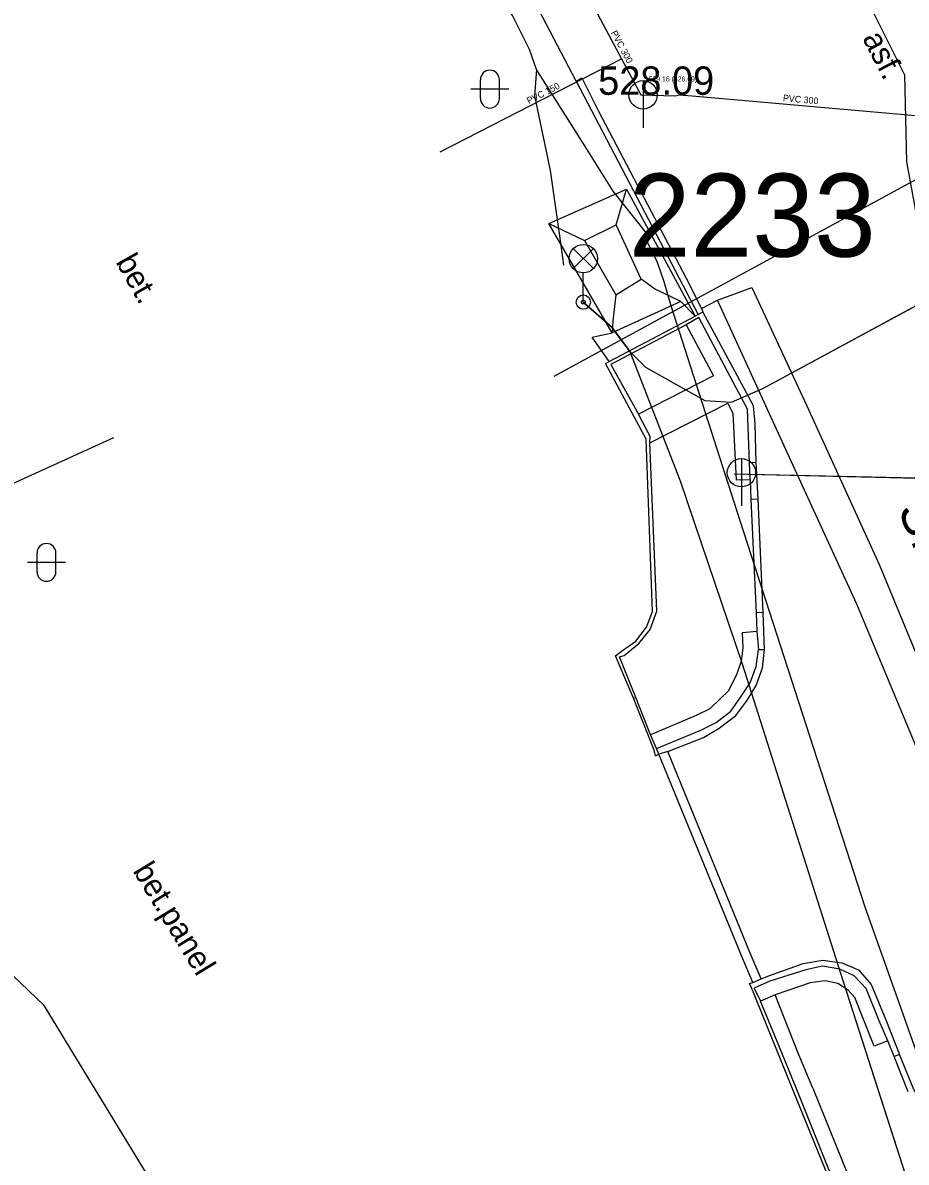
# Model space of a CAD drawing. Extents: x -669393 to -668650, y -1126925 to -1126294.
# Drawn here: x -669014.21 to -668990.85, y -1126829.82 to -1126799.71 of the extents above; entities that cross this region are included whole.
import ezdxf

# ---------------------------------------------------------------- set-up
doc = ezdxf.new("R2010")
doc.units = 0
for name, color, linetype in [('G_Bod_tecka', 7, 'Continuous'), ('G_Bod_vyska', 7, 'Continuous'), ('G_Cesty_Schody', 7, 'Continuous'), ('G_Objekty_technicke', 7, 'Continuous'), ('G_Plochy_zpevnene', 7, 'Continuous'), ('G_Popisy_Nazvy', 7, 'Continuous'), ('G_Popisy_povrchu', 7, 'Continuous'), ('G_Site-kanalizace', 7, 'Continuous'), ('G_Site-vodovod', 7, 'Continuous'), ('G_Z_ELsilove_podz_kotovane', 7, 'Continuous'), ('G_Z_KANAL_podz_kotovane', 7, 'Continuous'), ('G_Z_KANAL_podz_priblizne', 7, 'Continuous'), ('G_Z_PLYNY_podz_geodeticky', 7, 'Continuous'), ('G_Z_SPOJE_podz_geodeticky', 7, 'Continuous'), ('G_Z_SPOJE_podz_kotovane', 7, 'Continuous'), ('G_Z_SPOJE_podz_priblizne', 7, 'Continuous'), ('G_Zelen-Znacky', 7, 'Continuous'), ('Vrstva 1', 7, 'Continuous'), ('Vrstva 12', 7, 'Continuous'), ('Vrstva 13', 7, 'Continuous'), ('Vrstva 18', 7, 'Continuous'), ('Vrstva 2', 7, 'Continuous'), ('Vrstva 3', 7, 'Continuous'), ('Vrstva 4', 7, 'Continuous'), ('Vrstva 62', 7, 'Continuous'), ('Vrstva 8', 7, 'Continuous')]:
    doc.layers.add(name, color=color, linetype=linetype)

msp = doc.modelspace()

# ---------------------------------------------------------------- linework, layer by layer
at = {"layer": 'G_Bod_tecka'}
msp.add_line((-668997.81, -1126801.61), (-668997.81, -1126801.61), dxfattribs=at)
at = {"layer": 'G_Cesty_Schody'}
for p, q in [((-668993.49, -1126795.89), (-668990.9, -1126801.08)), ((-668998.71, -1126808.66), (-668996.43, -1126807.46)), ((-668996.34, -1126807.5), (-668996.67, -1126807.69)), ((-668994.82, -1126811.33), (-668995, -1126811.34)), ((-668994.77, -1126812.3), (-668994.96, -1126812.31)), ((-668991.56, -1126814.04), (-668986.09, -1126827.35)), ((-668989.88, -1126820.56), (-668992.16, -1126815.07)), ((-668994.64, -1126815.29), (-668994.82, -1126815.3)), ((-668998.06, -1126817.56), (-668998, -1126817.54)), ((-668994.32, -1126825.4), (-668994.71, -1126825.57)), ((-668991.03, -1126826.98), (-668991.17, -1126827.03)), ((-668993.32, -1126827.87), (-668990.55, -1126834.71)), ((-668990.94, -1126834.86), (-668993.68, -1126828.08))]:
    msp.add_line(p, q, dxfattribs=at)
for points in [[(-668999.58, -1126801.25), (-668999.43, -1126801.16), (-668998.99, -1126802.04), (-668996.67, -1126806.46), (-668996.27, -1126807.26), (-668996.23, -1126807.35)], [(-668990.9, -1126801.08), (-668990.85, -1126803.38), (-668990.37, -1126805.97)], [(-669000.3, -1126805.01), (-668999.36, -1126805.46), (-668998.52, -1126805.05), (-668998.25, -1126804.1)], [(-668999.36, -1126805.46), (-668998.53, -1126806.9), (-668997.86, -1126806.48), (-668998.52, -1126805.05)], [(-668996.81, -1126807.07), (-668997.51, -1126806.74), (-668997.86, -1126806.48)], [(-668998.53, -1126806.9), (-668998.61, -1126807.58), (-668998.63, -1126807.9)], [(-668996.27, -1126807.26), (-668995.84, -1126807.04), (-668994.94, -1126806.7), (-668993.48, -1126809.83), (-668991.56, -1126814.04)], [(-668996.43, -1126807.46), (-668996.81, -1126807.07), (-668998.63, -1126807.9)], [(-668992.16, -1126815.07), (-668994.19, -1126810.66), (-668995.84, -1126807.04)], [(-668994.98, -1126811.78), (-668995, -1126811.34), (-668995.05, -1126809.92), (-668996.34, -1126807.5)], [(-668996.67, -1126807.69), (-668998.66, -1126808.74), (-668997.93, -1126810.05)], [(-668996.67, -1126807.69), (-668995.95, -1126809.04), (-668997.93, -1126810.05)], [(-668997.63, -1126810.81), (-668995.57, -1126809.76), (-668995.44, -1126810.03), (-668995.35, -1126811.79), (-668994.98, -1126811.78)], [(-668997.63, -1126810.81), (-668997.62, -1126810.64), (-668997.93, -1126810.05)], [(-668997.61, -1126818.53), (-668998, -1126817.54), (-668998.43, -1126816.47), (-668998.31, -1126816.43), (-668997.92, -1126816.11), (-668997.62, -1126815.74), (-668997.45, -1126815.26), (-668997.63, -1126810.81)], [(-668994.98, -1126811.78), (-668994.96, -1126812.31), (-668994.82, -1126815.3), (-668994.8, -1126815.8), (-668994.76, -1126816.27), (-668994.6, -1126816.27)], [(-668994.8, -1126815.8), (-668995.19, -1126815.83), (-668995.17, -1126816.23), (-668995.22, -1126816.58), (-668995.34, -1126816.94), (-668995.56, -1126817.37), (-668995.76, -1126817.57), (-668996.05, -1126817.84), (-668996.41, -1126818.02), (-668997.61, -1126818.53)], [(-668997.46, -1126818.89), (-668996.28, -1126818.4), (-668995.88, -1126818.2), (-668995.49, -1126817.9), (-668995.24, -1126817.55), (-668994.98, -1126817.15), (-668994.82, -1126816.72), (-668994.76, -1126816.27)], [(-668997.39, -1126819.04), (-668997.46, -1126818.89), (-668997.61, -1126818.53)], [(-668991.34, -1126826.62), (-668991.57, -1126826.09), (-668991.91, -1126825.23), (-668992.23, -1126824.9), (-668992.61, -1126824.72), (-668993.07, -1126824.64), (-668993.51, -1126824.74), (-668994.46, -1126825.04), (-668994.87, -1126825.22), (-668994.71, -1126825.57)], [(-668991.34, -1126826.62), (-668991.7, -1126826.76), (-668992.21, -1126825.47), (-668992.39, -1126825.28), (-668992.66, -1126825.1), (-668993, -1126825.03), (-668993.39, -1126825.08), (-668994.32, -1126825.4)], [(-668993.68, -1126828.08), (-668994.22, -1126826.74), (-668994.71, -1126825.57)], [(-668993.32, -1126827.87), (-668993.71, -1126826.94), (-668994.32, -1126825.4)], [(-668990.8, -1126827.96), (-668991.17, -1126827.03), (-668991.34, -1126826.62)]]:
    msp.add_lwpolyline(points, dxfattribs=at)
at = {"layer": 'G_Objekty_technicke'}
for p, q in [((-668999.655, -1126805.675), (-668999.125, -1126806.205)), ((-668999.655, -1126806.205), (-668999.125, -1126805.675)), ((-668999.39, -1126807.09), (-668999.39, -1126806.315))]:
    msp.add_line(p, q, dxfattribs=at)
for centre, radius in [((-668999.39, -1126805.94), 0.375), ((-668999.39, -1126807.09), 0.19), ((-668999.39, -1126807.09), 0.05)]:
    msp.add_circle(centre, radius, dxfattribs=at)
at = {"layer": 'G_Plochy_zpevnene'}
for p, q in [((-668999.58, -1126801.25), (-668996.35, -1126807.42)), ((-668996.35, -1126807.42), (-668996.43, -1126807.46)), ((-668996.35, -1126807.42), (-668996.23, -1126807.35)), ((-668994.77, -1126812.3), (-668994.82, -1126811.33)), ((-668994.64, -1126815.29), (-668994.77, -1126812.3)), ((-668994.6, -1126816.27), (-668994.64, -1126815.29)), ((-668997.48, -1126819.08), (-668997.39, -1126819.04)), ((-668995, -1126825.1), (-668994.91, -1126825.07)), ((-668990.99, -1126834.92), (-668993.76, -1126828.12))]:
    msp.add_line(p, q, dxfattribs=at)
for points in [[(-668999.58, -1126801.25), (-669001.65, -1126797.28), (-669004.25, -1126792.55)], [(-668998.63, -1126807.9), (-669000.3, -1126805.01), (-668998.25, -1126804.1), (-668996.43, -1126807.46)], [(-668994.82, -1126811.33), (-668994.85, -1126810.31), (-668994.89, -1126809.83), (-668996.23, -1126807.35)], [(-668998.71, -1126808.66), (-668999.16, -1126808.02), (-668998.63, -1126807.9)], [(-668998.06, -1126817.56), (-668998.54, -1126816.44), (-668998.38, -1126816.32), (-668998, -1126816.05), (-668997.72, -1126815.68), (-668997.56, -1126815.27), (-668997.73, -1126810.71), (-668998.8, -1126808.71), (-668998.71, -1126808.66)], [(-669011.81, -1126810.68), (-669025.44, -1126816.88), (-669022.47, -1126822.11)], [(-668997.16, -1126818.97), (-668996.21, -1126818.6), (-668995.8, -1126818.35), (-668995.36, -1126818.02), (-668995.07, -1126817.63), (-668994.82, -1126817.22), (-668994.65, -1126816.76), (-668994.6, -1126816.27)], [(-668997.48, -1126819.08), (-668997.52, -1126818.93), (-668998.06, -1126817.56)], [(-668990.86, -1126836.84), (-668993.75, -1126838.26), (-668997.48, -1126831.06), (-669010.3, -1126831.16), (-669013.64, -1126825.68), (-669019.22, -1126820.35), (-669022.47, -1126822.11)], [(-668994.69, -1126824.98), (-668994.49, -1126824.9), (-668993.58, -1126824.57), (-668993.06, -1126824.48), (-668992.56, -1126824.55), (-668992.12, -1126824.74), (-668991.78, -1126825.13), (-668991.39, -1126826.06), (-668991.03, -1126826.98)], [(-668993.76, -1126828.12), (-668994.94, -1126825.23), (-668995, -1126825.1)], [(-668990.17, -1126828.75), (-668990.65, -1126827.9), (-668991.03, -1126826.98)]]:
    msp.add_lwpolyline(points, dxfattribs=at)
at = {"layer": 'G_Site-kanalizace'}
for p, q in [((-668997.81, -1126801.235), (-668997.81, -1126802.485)), ((-668997.16, -1126818.97), (-668997.39, -1126819.04)), ((-668994.98, -1126824.3), (-668997.16, -1126818.97)), ((-668995.2, -1126824.39), (-668997.39, -1126819.04)), ((-668994.91, -1126825.07), (-668995.2, -1126824.39))]:
    msp.add_line(p, q, dxfattribs=at)
msp.add_lwpolyline([(-668994.91, -1126825.07), (-668994.69, -1126824.98), (-668994.98, -1126824.3)], dxfattribs=at)
msp.add_circle((-668997.81, -1126801.61), 0.375, dxfattribs=at)
at = {"layer": 'G_Site-vodovod'}
msp.add_line((-668995.21, -1126811.225), (-668995.21, -1126812.475), dxfattribs=at)
msp.add_circle((-668995.21, -1126811.6), 0.375, dxfattribs=at)
at = {"layer": 'G_Z_ELsilove_podz_kotovane'}
for points in [[(-668998.15, -1126808.4), (-668997.75, -1126808.81), (-668996.18, -1126809.69), (-668995.47, -1126809.73), (-668994.63, -1126809.36), (-668989.09, -1126806.37), (-668987.42, -1126805.75), (-668985.59, -1126805.39), (-668983.91, -1126805.11), (-668986.31, -1126798.78)], [(-668998.15, -1126808.4), (-668998.63, -1126807.76), (-668999.39, -1126807.09), (-668998.64, -1126807.75), (-668998.15, -1126808.4)], [(-669017.66, -1126872.32), (-669017.32, -1126872.52), (-669016.99, -1126872.74), (-669016.2, -1126873.79), (-669014.59, -1126874.31), (-669011.9, -1126874.39), (-669008.01, -1126874.21), (-669004.03, -1126873.7), (-668998.67, -1126872.68), (-668990.7, -1126870.94), (-668986.65, -1126870.22), (-668983.44, -1126869.78), (-668982.61, -1126869.01), (-668983.07, -1126861.94), (-668985.62, -1126845.02), (-668988.11, -1126838.21), (-668989.92, -1126833.67), (-668990.48, -1126832.73), (-668990.47, -1126831.41), (-668992.59, -1126824.81), (-668995.18, -1126816.66), (-668996.82, -1126811.82), (-668998.15, -1126808.4)]]:
    msp.add_lwpolyline(points, dxfattribs=at)
at = {"layer": 'G_Z_KANAL_podz_kotovane'}
msp.add_line((-669003.17, -1126803.12), (-668998.38, -1126800.66), dxfattribs=at)
for points in [[(-669021.5, -1126757.31), (-669019.78, -1126760.55), (-669002.4, -1126793.12), (-668998.38, -1126800.66), (-668997.87, -1126801.61)], [(-668997.87, -1126801.61), (-668996.96, -1126801.64), (-668996.86, -1126801.61), (-668996.51, -1126801.64), (-668986.9, -1126802.48), (-668982.92, -1126802.9)]]:
    msp.add_lwpolyline(points, dxfattribs=at)
at = {"layer": 'G_Z_KANAL_podz_priblizne'}
msp.add_line((-668995.4, -1126811.63), (-668959.75, -1126812.45), dxfattribs=at)
at = {"layer": 'G_Z_PLYNY_podz_geodeticky'}
msp.add_lwpolyline([(-668985.69, -1126793.26), (-668988.48, -1126802.69), (-668988.74, -1126802.84), (-668997.09, -1126807.38), (-669000.17, -1126809.06)], dxfattribs=at)
at = {"layer": 'G_Z_SPOJE_podz_geodeticky'}
for points in [[(-669000.63, -1126800.94), (-669000.81, -1126800.41), (-669001.26, -1126799.51), (-669001.63, -1126798.96)], [(-669000.63, -1126800.94), (-669000.68, -1126801.64), (-669000.27, -1126803.61), (-669000.02, -1126805.34), (-668999.91, -1126806.11)], [(-668998.6, -1126804.16), (-668999.31, -1126803.03), (-669000.63, -1126800.94)], [(-668985.02, -1126843.63), (-668988.57, -1126832.56), (-668991.94, -1126823.08), (-668995.24, -1126812.87), (-668997.08, -1126807.16), (-668997.25, -1126806.55), (-668997.43, -1126806.04), (-668997.68, -1126805.54), (-668997.75, -1126805.23), (-668998.6, -1126804.16)]]:
    msp.add_lwpolyline(points, dxfattribs=at)
at = {"layer": 'G_Z_SPOJE_podz_kotovane'}
msp.add_lwpolyline([(-669000.63, -1126800.94), (-669000.68, -1126801.64), (-669000.27, -1126803.61), (-669000.02, -1126805.34), (-668999.91, -1126806.11)], dxfattribs=at)
at = {"layer": 'G_Z_SPOJE_podz_priblizne'}
msp.add_lwpolyline([(-669000.63, -1126800.94), (-669000.68, -1126801.64), (-669000.27, -1126803.61), (-669000.02, -1126805.34), (-668999.91, -1126806.11)], dxfattribs=at)
at = {"layer": 'G_Zelen-Znacky'}
for p, q in [((-669002.11, -1126801.71), (-669002.11, -1126801.21)), ((-669001.61, -1126801.71), (-669001.61, -1126801.21)), ((-669001.36, -1126801.46), (-669002.36, -1126801.46)), ((-669013.83, -1126814.22), (-669013.83, -1126813.72)), ((-669013.33, -1126814.22), (-669013.33, -1126813.72)), ((-669013.08, -1126813.97), (-669014.08, -1126813.97))]:
    msp.add_line(p, q, dxfattribs=at)
for centre, start, end in [((-669001.86, -1126801.21), 0, 180), ((-669001.86, -1126801.71), 180, 0), ((-669013.58, -1126813.72), 0, 180), ((-669013.58, -1126814.22), 180, 0)]:
    msp.add_arc(centre, 0.25, start, end, dxfattribs=at)
at = {"layer": 'Vrstva 1'}
msp.add_line((-668999.39, -1126807.09), (-668999.39, -1126807.09), dxfattribs=at)
at = {"layer": 'Vrstva 12'}
for points in [[(-669021.5, -1126757.31), (-669019.78, -1126760.55), (-669002.4, -1126793.125), (-668998.377, -1126800.659), (-668997.87, -1126801.61)], [(-668997.87, -1126801.61), (-668996.96, -1126801.64), (-668996.86, -1126801.61), (-668996.512, -1126801.64), (-668986.9, -1126802.48), (-668982.92, -1126802.9)]]:
    msp.add_lwpolyline(points, dxfattribs=at)
at = {"layer": 'Vrstva 13'}
msp.add_line((-669003.17, -1126803.12), (-668998.377, -1126800.659), dxfattribs=at)
at = {"layer": 'Vrstva 18'}
msp.add_line((-668995.402, -1126811.627), (-668959.749, -1126812.446), dxfattribs=at)
at = {"layer": 'Vrstva 62'}
for p, q in [((-668994.63, -1126809.36), (-668989.09, -1126806.37)), ((-668998.629, -1126807.765), (-668999.39, -1126807.09)), ((-668999.39, -1126807.09), (-668998.64, -1126807.75)), ((-668998.64, -1126807.75), (-668998.15, -1126808.4)), ((-668998.15, -1126808.4), (-668998.629, -1126807.765)), ((-668996.82, -1126811.82), (-668998.15, -1126808.4)), ((-668998.15, -1126808.4), (-668997.746, -1126808.81)), ((-668997.746, -1126808.81), (-668996.18, -1126809.69)), ((-668995.47, -1126809.73), (-668994.63, -1126809.36)), ((-668996.18, -1126809.69), (-668995.47, -1126809.73)), ((-668995.18, -1126816.66), (-668996.82, -1126811.82)), ((-668992.59, -1126824.81), (-668995.18, -1126816.66)), ((-668990.47, -1126831.41), (-668992.59, -1126824.81))]:
    msp.add_line(p, q, dxfattribs=at)
at = {"layer": 'Vrstva 8'}
msp.add_line((-668997.87, -1126801.61), (-668997.87, -1126801.61), dxfattribs=at)

# ---------------------------------------------------------------- texts
at = {"layer": 'G_Bod_vyska'}
msp.add_text('528.09', height=0.75, dxfattribs=at).set_placement((-668998.998, -1126801.61))
at = {"layer": 'G_Popisy_Nazvy'}
msp.add_text('SMRCENSKA', height=1, rotation=292.3412, dxfattribs=at).set_placement((-668991.086, -1126812.56))
at = {"layer": 'G_Popisy_povrchu'}
for s, rotation, p in [('asf.', 297.2515, (-668992.023, -1126800.112)), ('bet.', 299.5761, (-669011.763, -1126806.026)), ('bet.panel', 301.3619, (-669011.311, -1126822.121))]:
    msp.add_text(s, height=0.6, rotation=rotation, dxfattribs=at).set_placement(p)
at = {"layer": 'Vrstva 2'}
msp.add_text('529.16 (526.69)', height=0.13163, dxfattribs=at).set_placement((-668997.664, -1126801.257))
at = {"layer": 'Vrstva 3'}
for s, rotation, p in [('PVC 300', 298.1305, (-668998.667, -1126799.968)), ('PVC 150', 27.1885, (-669000.828, -1126801.859)), ('PVC 300', 354.9964, (-668994.119, -1126801.778))]:
    msp.add_text(s, height=0.1755, rotation=rotation, dxfattribs=at).set_placement(p)
at = {"layer": 'Vrstva 4'}
msp.add_text('2233', height=2.1939, dxfattribs=at).set_placement((-668998.187, -1126805.888))

doc.saveas('drawing.dxf')
